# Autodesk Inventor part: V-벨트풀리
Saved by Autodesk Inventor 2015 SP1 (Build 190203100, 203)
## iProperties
Created: 2026-07
Part Number: V-벨트풀리
Material: 일반
Document SubType Name: Modeling
Designer: user
Density: 1 g/cm^3
Appearance: 기본값
Author: user
Author: jhkim
Creation Date: 2026-07-01
Sending System: Autodesk Inventor 2027
Preprocessor: ST-DEVELOPER v20.1
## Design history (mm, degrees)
node "V-벨트풀리1"
body "Solid1"
node "기준1"
